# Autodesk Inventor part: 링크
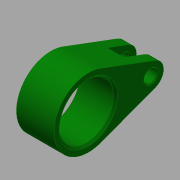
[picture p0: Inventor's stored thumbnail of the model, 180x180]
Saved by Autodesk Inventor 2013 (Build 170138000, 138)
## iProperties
Created: 2016-08
Part Number: 링크
Material: 강철, 탄소
Document SubType Name: Modeling
Designer: mduedu
Density: 7.87 g/cm^3
Author: mduedu
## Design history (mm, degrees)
sketch "스케치1"
  geometry: L1 (32.1, 5.62)-(5.775, 15.456); L2 (32.1, -5.62)-(5.775, -15.456); C1 r 13 at (0, 0); C2 r 3 at (30, 0); A1 r 16.5 centre (0, 0) between (5.775, 15.456) and (5.775, -15.456); A2 r 6 centre (30, 0) between (32.1, 5.62) and (32.1, -5.62); 1 further point
  constraints: 4 centre point, 4 end point, 4 point on circle, 4 tangent, 3 coincident, 1 horizontal alignment
  dimensions: "d0" = 33 diameter of A1; "d2" = 12 diameter of A2; "d3" = 30 distance of A2.centre point (0, 0); "d4" = 26 diameter of C1; "d5" = 6 diameter of C2
extrude "돌출1" new body sketch "스케치1" stored distance "d6" = 18; taper "d7" = 0 deg
sketch "스케치2"
  geometry: L1 (-9, 36)-(9, 36) reference; L2 (0, 0)-(0, 36); L3 (-4, 36)-(4, 36); L4 (4, 36)-(4, 22); L5 (4, 22)-(-4, 22); L6 (-4, 22)-(-4, 36)
  constraints: 10 end point, 2 midpoint, 2 parallel, 1 horizontal, 1 perpendicular, 1 point on line
  dimensions: "d8" = 8 distance between parallel lines of L4 L6; "d10" = 14 distance of L3.end L4.end
extrude "돌출2" cut sketch "스케치2" stored distance "d11" = 20; taper "d12" = 0 deg
chamfer "모따기1" distance "d13" = 1; stored, may be unused: second distance "d14" = 2, angle "d15" = 45 deg
chamfer "모따기2" distance "d16" = 0.5; stored, may be unused: second distance "d17" = 2, angle "d18" = 45 deg
node "솔리드1"
